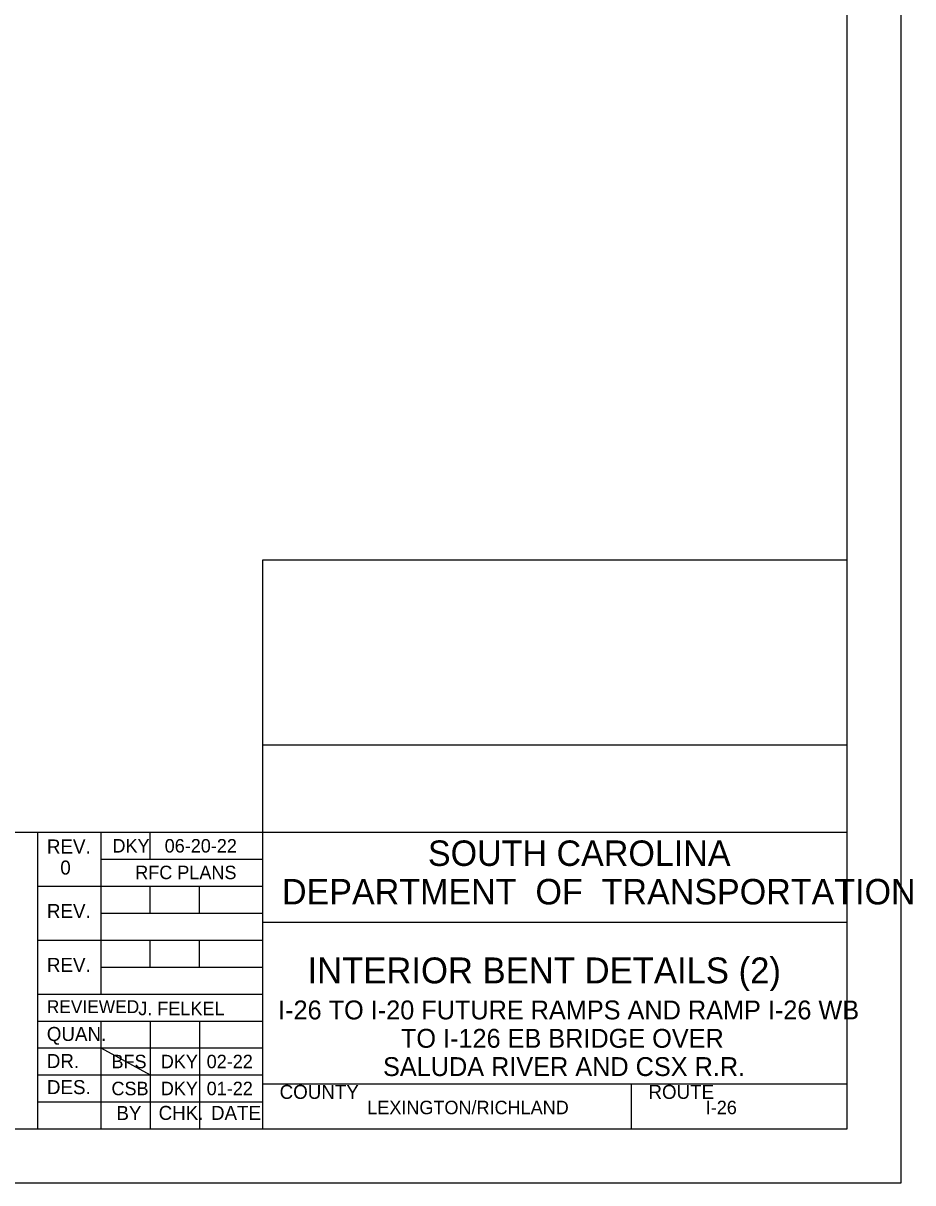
# Model space of a CAD drawing. Extents: x -133.1 to -97, y -1.7 to 20.3.
# Drawn here: x -105.28 to -97.03, y -1.69 to 9.06 of the extents above; entities that cross this region are included whole.
import ezdxf

# ---------------------------------------------------------------- set-up
doc = ezdxf.new("R2010")
doc.units = 0
for name, color, linetype in [('BR_BORDER LINES', 7, 'Continuous'), ('BR_TEXT', 7, 'Continuous'), ('Level 31', 7, 'Continuous')]:
    doc.layers.add(name, color=color, linetype=linetype)

msp = doc.modelspace()

# ---------------------------------------------------------------- linework, layer by layer
at = {"layer": 'BR_BORDER LINES'}
for p, q in [((-97.642, -1.191), (-97.642, 19.809)), ((-103.058, 4.086), (-97.642, 4.086)), ((-103.058, -1.191), (-103.058, 4.086)), ((-103.058, 4.086), (-97.642, 4.086)), ((-103.058, 2.371), (-97.642, 2.371)), ((-110.507, 1.559), (-105.142, 1.559)), ((-105.142, -1.191), (-105.142, 1.559)), ((-105.142, 1.559), (-97.642, 1.559)), ((-104.559, 1.559), (-104.559, 0.059)), ((-104.1, 1.309), (-104.1, 1.559)), ((-104.559, 1.309), (-103.058, 1.309)), ((-105.142, 1.059), (-103.058, 1.059)), ((-104.1, 0.809), (-104.1, 1.059)), ((-103.642, 0.809), (-103.642, 1.059)), ((-104.559, 0.809), (-103.058, 0.809)), ((-103.058, 0.726), (-103.058, 0.726)), ((-103.058, 0.726), (-97.641, 0.726)), ((-105.142, 0.559), (-103.058, 0.559)), ((-104.1, 0.309), (-104.1, 0.559)), ((-103.642, 0.309), (-103.642, 0.559)), ((-104.559, 0.309), (-103.058, 0.309)), ((-105.142, 0.059), (-103.058, 0.059)), ((-105.142, -0.191), (-103.058, -0.191)), ((-104.559, -0.191), (-104.559, -1.191)), ((-104.1, -0.191), (-104.1, -1.191)), ((-103.642, -0.191), (-103.642, -1.191)), ((-105.142, -0.441), (-103.058, -0.441)), ((-105.142, -0.691), (-103.058, -0.691)), ((-103.058, -0.774), (-97.642, -0.774)), ((-102.961, -0.774), (-97.642, -0.774)), ((-99.642, -1.191), (-99.642, -0.774)), ((-105.142, -0.941), (-103.058, -0.941)), ((-131.308, -1.191), (-97.642, -1.191))]:
    msp.add_line(p, q, dxfattribs=at)
at = {"layer": 'Level 31'}
for p, q in [((-100.35, 0.285), (-100.35, 0.285)), ((-104.559, -0.441), (-104.1, -0.691))]:
    msp.add_line(p, q, dxfattribs=at)
msp.add_lwpolyline([(-133.141, -1.691), (-97.141, -1.691), (-97.141, 20.309), (-133.141, 20.309)], close=True, dxfattribs=at)

# ---------------------------------------------------------------- texts
at = {"layer": 'BR_TEXT'}
for s, height, p in [('REV.', 0.13, (-105.057, 1.362)), ('DKY', 0.125, (-104.45, 1.371)), ('06-20-22', 0.125, (-103.966, 1.371)), ('SOUTH CAROLINA', 0.23587, (-101.527, 1.247)), ('0', 0.13, (-104.933, 1.167)), ('RFC PLANS', 0.125, (-104.239, 1.124)), ('DEPARTMENT  OF  TRANSPORTATION', 0.23587, (-102.879, 0.89)), ('REV.', 0.13, (-105.057, 0.764)), ('REV.', 0.13, (-105.057, 0.264)), ('INTERIOR BENT DETAILS (2)', 0.24, (-102.643, 0.158)), ('REVIEWED', 0.12, (-105.058, -0.118)), ('I-26 TO I-20 FUTURE RAMPS AND RAMP I-26 WB', 0.175, (-102.915, -0.176)), ('J. FELKEL', 0.125, (-104.211, -0.137)), ('QUAN.', 0.13, (-105.058, -0.376)), ('TO I-126 EB BRIDGE OVER', 0.175, (-101.777, -0.439)), ('DR.', 0.13, (-105.058, -0.627)), ('BFS', 0.125, (-104.459, -0.629)), ('DKY', 0.125, (-104.002, -0.629)), ('02-22', 0.125, (-103.577, -0.629)), ('SALUDA RIVER AND CSX R.R.', 0.175, (-101.943, -0.701)), ('DES.', 0.13, (-105.057, -0.869)), ('CSB', 0.125, (-104.459, -0.879)), ('01-22', 0.125, (-103.577, -0.879)), ('DKY', 0.125, (-104.002, -0.879)), ('COUNTY', 0.13, (-102.901, -0.913)), ('ROUTE', 0.13, (-99.484, -0.913)), ('LEXINGTON/RICHLAND', 0.12499, (-102.089, -1.055)), ('I-26', 0.125, (-98.953, -1.055)), ('BY', 0.13, (-104.413, -1.109)), ('CHK.', 0.13, (-104.022, -1.108)), ('DATE', 0.13, (-103.537, -1.108))]:
    msp.add_text(s, height=height, dxfattribs=at).set_placement(p)

doc.saveas('drawing.dxf')
